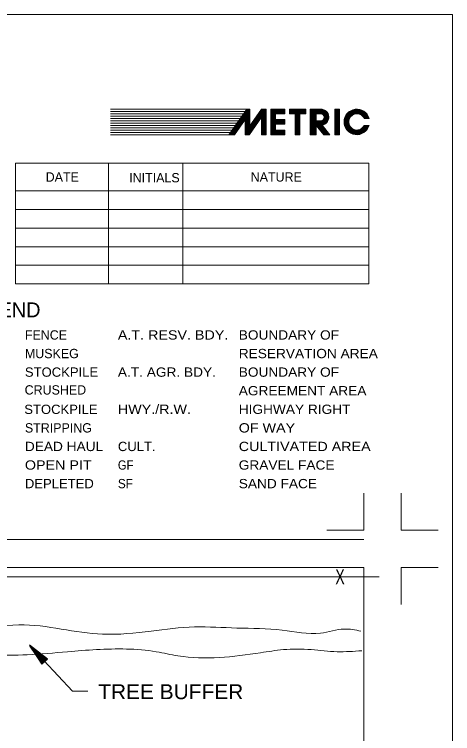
# Model space of a CAD drawing. Extents: x -496 to 480, y -450 to 700.
# Drawn here: x 214.3 to 450, y 312.9 to 700 of the extents above; entities that cross this region are included whole.
import ezdxf
from ezdxf.enums import TextEntityAlignment as Align

# ---------------------------------------------------------------- set-up
doc = ezdxf.new("R2010")
doc.units = 0
doc.header["$LTSCALE"] = 2
for name, color, linetype, lineweight in [('1', 7, 'Continuous', 13), ('3', 7, 'Continuous', 13), ('4', 7, 'Continuous', 25)]:
    doc.layers.add(name, color=color, linetype=linetype, lineweight=lineweight)

msp = doc.modelspace()

# ---------------------------------------------------------------- linework, layer by layer
at = {"layer": '1'}
for p, q in [((339.376, 648.989), (265.976, 648.989)), ((338.501, 647.739), (265.976, 647.739)), ((337.626, 646.489), (265.976, 646.489)), ((329.726, 635.239), (339.376, 648.989)), ((340.976, 640.064), (347.226, 648.989)), ((349.726, 648.989), (347.226, 648.989)), ((349.726, 635.239), (349.726, 648.989)), ((354.726, 646.489), (354.726, 643.364)), ((362.226, 648.989), (362.226, 646.489)), ((362.226, 646.489), (365.351, 646.489)), ((367.851, 646.489), (370.976, 646.489)), ((379.026, 648.989), (373.476, 648.989)), ((376.601, 646.489), (379.151, 646.489)), ((376.601, 642.739), (376.601, 646.489)), ((336.751, 645.239), (265.976, 645.239)), ((335.876, 643.989), (265.976, 643.989)), ((335.001, 642.739), (265.976, 642.739)), ((332.776, 635.239), (338.476, 643.364)), ((338.476, 635.239), (338.476, 643.389)), ((340.676, 635.264), (347.226, 644.614)), ((347.226, 635.239), (347.226, 644.614)), ((376.601, 642.739), (379.151, 642.739)), ((402.426, 643.989), (405.076, 643.989)), ((334.126, 641.489), (265.976, 641.489)), ((333.251, 640.239), (265.976, 640.239)), ((332.376, 638.989), (265.976, 638.989)), ((354.726, 640.864), (354.726, 637.739)), ((376.601, 640.239), (380.726, 635.239)), ((376.601, 635.239), (376.601, 640.239)), ((379.801, 640.289), (383.951, 635.239)), ((402.426, 640.239), (405.101, 640.239)), ((331.501, 637.739), (265.976, 637.739)), ((330.626, 636.489), (265.976, 636.489)), ((329.726, 635.239), (265.976, 635.239)), ((329.726, 635.239), (332.776, 635.239)), ((338.476, 635.239), (340.676, 635.239)), ((349.726, 635.239), (347.226, 635.239)), ((352.226, 635.239), (359.726, 635.239)), ((380.726, 635.239), (383.951, 635.239)), ((404.983, 619.973), (214.983, 619.973)), ((214.983, 619.973), (214.983, 554.973)), ((264.983, 619.973), (264.983, 554.973)), ((304.983, 619.973), (304.983, 554.973)), ((404.983, 554.973), (404.983, 619.973)), ((214.983, 604.973), (404.983, 604.973)), ((214.983, 594.973), (404.983, 594.973)), ((214.983, 584.973), (404.983, 584.973)), ((214.983, 574.973), (404.983, 574.973)), ((214.983, 564.973), (404.983, 564.973)), ((214.983, 554.973), (404.983, 554.973)), ((402.281, 422.339), (402.281, 442.339)), ((422.281, 422.339), (422.281, 442.339)), ((402.281, 422.339), (382.281, 422.339)), ((422.281, 422.339), (442.281, 422.339)), ((422.281, 402.339), (442.281, 402.339)), ((422.281, 402.339), (422.281, 382.339))]:
    msp.add_line(p, q, dxfattribs=at)
for points in [[(449.983, -450.027), (449.983, 399.973), (449.983, 699.973), (-450.017, 699.973), (-450.017, 49.973), (-450.017, -450.027)], [(329.901, 635.339), (339.401, 648.889), (340.901, 648.889), (340.901, 639.839), (347.251, 648.839), (349.626, 648.889), (349.676, 635.339), (347.351, 635.314), (347.301, 644.789), (340.576, 635.339), (338.576, 635.314), (338.576, 643.539), (332.701, 635.339), (330.076, 635.314), (339.501, 648.739), (340.801, 648.739), (340.776, 639.664), (347.276, 648.664), (349.526, 648.739), (349.651, 635.564), (347.501, 635.464), (347.426, 644.989), (340.526, 635.489), (338.726, 635.439), (338.676, 643.764), (332.651, 635.464), (330.301, 635.439), (339.576, 648.539), (340.651, 648.564), (340.651, 639.489), (347.351, 648.489), (349.301, 648.564), (349.476, 635.739), (347.726, 635.639), (347.626, 645.314), (340.451, 635.714), (338.926, 635.639), (338.876, 644.139), (332.501, 635.689), (330.701, 635.639)], [(330.701, 635.639), (339.651, 648.239), (340.326, 648.264), (340.476, 639.239), (347.526, 648.239), (349.126, 648.289), (349.226, 635.939), (348.001, 635.939), (347.851, 645.664), (340.326, 635.989), (339.151, 635.864), (339.126, 644.464), (332.401, 635.939), (331.076, 635.839), (339.651, 647.914), (340.151, 647.914), (340.251, 638.889), (347.601, 647.964), (348.926, 648.014), (349.026, 636.164), (348.251, 636.139), (348.051, 646.014), (340.226, 636.239), (339.351, 636.089), (339.326, 644.789), (332.226, 636.164), (331.476, 636.064), (339.701, 647.664), (339.926, 647.689), (340.126, 638.764), (347.751, 647.839), (348.701, 647.739), (348.826, 636.364), (348.476, 636.364), (348.176, 646.314), (340.126, 636.464), (339.551, 636.339), (339.426, 645.114), (332.201, 636.339), (331.851, 636.289)], [(331.851, 636.289), (339.701, 647.264), (339.926, 638.564), (347.826, 647.614), (348.451, 647.589), (348.701, 636.589), (348.251, 646.639), (340.126, 636.689), (339.726, 636.589), (339.576, 645.539), (332.301, 636.639), (339.526, 646.714), (339.576, 645.814), (335.101, 640.239), (339.401, 646.164), (339.401, 645.914), (338.176, 644.289)], [(340.976, 640.039), (340.976, 648.989), (339.376, 648.989)], [(339.901, 638.414), (339.926, 636.839), (348.276, 646.889), (348.326, 647.439), (347.951, 647.439), (340.126, 638.539), (340.151, 637.314), (348.176, 647.064), (348.051, 647.214), (340.326, 638.539), (340.401, 637.839), (347.851, 646.839), (340.501, 638.639), (340.526, 638.389), (344.426, 642.914)], [(352.226, 635.239), (352.226, 648.989), (359.726, 648.989)], [(352.376, 648.914), (359.651, 648.864), (359.676, 646.614), (354.626, 646.589), (354.626, 643.289), (359.651, 643.289), (359.651, 640.989), (354.651, 640.939), (354.626, 637.614), (359.676, 637.639), (359.651, 635.339), (352.351, 635.314), (352.376, 648.789), (359.551, 648.739), (359.551, 646.764), (354.501, 646.714), (354.501, 643.214), (359.551, 643.164), (359.551, 641.114), (354.551, 641.064), (354.526, 637.439), (359.551, 637.514), (359.501, 635.439), (352.501, 635.439), (352.576, 648.639), (359.401, 648.564), (359.426, 646.914), (354.376, 646.839), (354.351, 643.064), (359.426, 643.039), (359.376, 641.289), (354.401, 641.239), (354.376, 637.239), (359.401, 637.339), (359.376, 635.589), (352.701, 635.614), (352.726, 648.439), (359.226, 648.414), (359.251, 647.064), (354.251, 647.039)], [(354.251, 647.039), (354.176, 642.864), (359.251, 642.864), (359.176, 641.439), (354.251, 641.389), (354.201, 637.064), (359.201, 637.114), (359.176, 635.739), (352.926, 635.814), (352.976, 648.214), (359.026, 648.239), (359.076, 647.289), (354.076, 647.214), (354.001, 642.689), (359.051, 642.664), (359.026, 641.639), (354.076, 641.564), (354.026, 636.864), (359.051, 636.939), (359.026, 635.989), (353.126, 636.039), (353.226, 647.989), (358.801, 648.039), (358.826, 647.464), (353.926, 647.389), (353.851, 642.489), (358.876, 642.539), (358.801, 641.814), (353.951, 641.689), (353.851, 636.714), (358.901, 636.764), (358.901, 636.214), (353.351, 636.214), (353.476, 647.714), (358.601, 647.889), (358.626, 647.639), (353.776, 647.514), (353.751, 642.364), (358.626, 642.389), (358.601, 642.014)], [(358.601, 642.014), (353.826, 641.864), (353.726, 636.564), (358.701, 636.639), (358.701, 636.389), (353.551, 636.439), (353.626, 641.989), (358.376, 642.164), (358.326, 642.289), (353.576, 642.264), (353.676, 647.564)], [(359.726, 648.989), (359.726, 646.489), (354.726, 646.489)], [(370.976, 646.489), (370.976, 648.989), (362.226, 648.989)], [(362.351, 648.864), (370.851, 648.889), (370.851, 646.639), (367.701, 646.639), (367.751, 635.414), (365.451, 635.314), (365.451, 646.564), (362.351, 646.589), (362.351, 648.764), (370.801, 648.789), (370.726, 646.789), (367.601, 646.764), (367.676, 635.539), (365.576, 635.414), (365.626, 646.739), (362.476, 646.739), (362.476, 648.639), (370.626, 648.639), (370.576, 646.989), (367.426, 646.864), (367.526, 635.739), (365.751, 635.614), (365.776, 646.864), (362.701, 646.939), (362.726, 648.439), (370.451, 648.489), (370.376, 647.114), (367.276, 646.989), (367.376, 635.914), (365.901, 635.789), (365.951, 647.064), (362.901, 647.114), (362.901, 648.264), (370.201, 648.289), (370.201, 647.364), (367.076, 647.189), (367.226, 636.114), (366.126, 635.989), (366.101, 647.264), (363.101, 647.314)], [(363.101, 647.314), (363.151, 648.089), (369.976, 648.164), (369.926, 647.489), (366.876, 647.364), (367.026, 636.339), (366.351, 636.239), (366.276, 647.439), (363.326, 647.514), (363.401, 647.939), (369.751, 648.039), (369.701, 647.714), (366.726, 647.539), (366.851, 636.564), (366.476, 636.489), (366.426, 647.664), (363.701, 647.664), (363.751, 647.839), (369.451, 647.914), (369.426, 647.814), (366.601, 647.664), (366.626, 636.689)], [(367.851, 646.489), (367.851, 635.239), (365.351, 635.239), (365.351, 646.489)], [(373.476, 648.989), (373.476, 635.239), (376.601, 635.239)], [(373.601, 648.914), (378.976, 648.889), (380.101, 648.739), (381.101, 648.364), (381.826, 647.789), (382.451, 647.189), (382.901, 646.414), (383.301, 645.389), (383.301, 644.439), (383.126, 643.214), (382.651, 642.314), (381.926, 641.489), (381.051, 640.889), (380.401, 640.639), (379.651, 640.389), (380.026, 639.714), (380.576, 639.189), (383.701, 635.339), (380.801, 635.314), (376.501, 640.464), (376.526, 635.339), (373.551, 635.314), (373.551, 648.864), (379.026, 648.789), (380.076, 648.639), (380.926, 648.314), (382.276, 647.214), (383.151, 645.364), (383.026, 643.314), (382.601, 642.464), (381.901, 641.614), (381.051, 640.989), (379.576, 640.464), (383.501, 635.414), (380.951, 635.439), (376.351, 640.739), (376.401, 635.489), (373.701, 635.439), (373.701, 648.739), (379.151, 648.664), (380.076, 648.489), (380.851, 648.189), (382.126, 647.139), (383.026, 645.389), (382.951, 643.539), (382.501, 642.564), (381.901, 641.739), (381.051, 641.114), (379.401, 640.614), (383.201, 635.564), (381.001, 635.564), (376.226, 640.889), (376.276, 635.614), (373.826, 635.539), (373.826, 648.614), (379.126, 648.489), (380.676, 648.089), (382.026, 647.139), (382.876, 645.439), (382.801, 643.664), (382.401, 642.664), (381.801, 641.889), (380.951, 641.189), (379.226, 640.764), (382.901, 635.689), (381.101, 635.689), (376.051, 641.064), (376.126, 635.789), (373.976, 635.689), (373.976, 648.439), (379.101, 648.364), (380.551, 647.989), (381.851, 647.089), (382.776, 645.439), (382.701, 643.764), (382.326, 642.889), (381.726, 642.064), (380.901, 641.339), (379.026, 640.939), (382.601, 635.789), (381.126, 635.814), (375.876, 641.239), (375.976, 635.939), (374.126, 635.864), (374.126, 648.239), (379.026, 648.239), (380.251, 647.914), (381.676, 647.014), (382.576, 645.414), (382.601, 643.914), (382.276, 642.989), (381.651, 642.214), (380.826, 641.514), (378.851, 641.064), (382.351, 635.939), (381.176, 635.989), (375.776, 641.514), (375.826, 636.089), (374.251, 636.014), (374.276, 648.039), (378.976, 648.114)], [(378.976, 648.114), (379.026, 648.114), (380.201, 647.764), (381.526, 646.939), (382.401, 645.489), (382.401, 643.964), (382.076, 643.114), (380.826, 641.764), (378.601, 641.264), (382.001, 636.114), (381.351, 636.114), (375.676, 641.789), (375.676, 636.264), (374.376, 636.189), (374.451, 647.864), (378.926, 647.939), (380.176, 647.689), (381.351, 646.914), (382.151, 645.414), (382.201, 644.014), (381.901, 643.214), (380.726, 641.989), (378.401, 641.389), (381.676, 636.314), (381.501, 636.189), (375.526, 642.064), (375.476, 636.414), (374.551, 636.339), (374.651, 647.739), (379.976, 647.614), (381.151, 646.914), (382.001, 645.414), (382.051, 644.139), (381.726, 643.339), (380.651, 642.139), (378.226, 641.589), (381.401, 636.464), (375.401, 642.364), (375.376, 636.614), (374.676, 636.539), (374.901, 647.589), (379.826, 647.414), (380.851, 646.889), (381.801, 645.439), (381.901, 644.389), (381.576, 643.539), (380.576, 642.414), (378.051, 641.739), (380.676, 637.364), (375.376, 642.614), (375.226, 636.739), (374.851, 636.739), (375.076, 647.339), (379.601, 647.314), (380.676, 646.839), (381.626, 645.414), (381.726, 644.464), (381.376, 643.589), (380.501, 642.589), (377.826, 641.864), (380.026, 638.189), (375.251, 642.889), (375.076, 636.939), (374.926, 636.989), (375.226, 647.189), (379.526, 647.139), (380.551, 646.714), (381.401, 645.414), (381.551, 644.614), (380.376, 642.739), (377.726, 642.039), (379.276, 639.239), (375.351, 643.039), (375.426, 646.989), (379.476, 646.989), (380.526, 646.639), (381.251, 645.489), (381.326, 644.614), (380.276, 642.914), (377.551, 642.239), (378.601, 640.139), (375.576, 643.139), (375.676, 646.839), (379.451, 646.839), (380.476, 646.514), (381.101, 645.414), (381.051, 644.489), (380.876, 645.464), (380.501, 646.039), (380.151, 646.339), (379.476, 646.514), (378.751, 646.639), (377.601, 646.614), (376.476, 646.614), (376.501, 642.714), (378.626, 642.664), (377.376, 642.339), (378.126, 640.764), (375.726, 643.164), (375.876, 646.714), (379.451, 646.714)], [(376.026, 646.614), (375.901, 643.214), (377.551, 641.614), (377.251, 642.364), (377.776, 642.614), (376.826, 642.614), (377.201, 642.164)], [(376.151, 646.564), (376.051, 643.314), (376.376, 643.064), (376.351, 646.564), (376.251, 643.389)], [(379.451, 646.714), (379.401, 646.739), (380.451, 646.289)], [(386.776, 648.839), (388.951, 648.864), (389.001, 635.364), (386.701, 635.364), (386.676, 648.739), (388.851, 648.764), (388.876, 635.489), (386.826, 635.439), (386.801, 648.614), (388.776, 648.639), (388.776, 635.664), (386.976, 635.589), (386.926, 648.464), (388.626, 648.464), (388.601, 635.764), (387.126, 635.764), (387.101, 648.364), (388.501, 648.364), (388.451, 635.939), (387.301, 635.964), (387.301, 648.214), (388.401, 648.214), (388.301, 636.089), (387.426, 636.089), (387.476, 648.064), (388.251, 648.039), (388.151, 636.214), (387.576, 636.214), (387.676, 647.914), (388.126, 647.889), (388.001, 636.339), (387.776, 636.389), (387.826, 647.764), (387.976, 647.714), (387.901, 636.539)], [(404.901, 644.089), (404.451, 645.189), (403.851, 646.164), (403.151, 646.914), (402.301, 647.639), (401.151, 648.289), (400.126, 648.614), (398.801, 648.814), (397.351, 648.689), (395.876, 648.339), (394.601, 647.639), (393.601, 646.764), (392.776, 645.664), (392.176, 644.564), (391.801, 642.964), (391.801, 641.264), (392.176, 639.789), (392.726, 638.564), (393.351, 637.739), (394.101, 637.014), (394.976, 636.389), (395.901, 635.914), (397.126, 635.489), (398.726, 635.389), (400.151, 635.589), (401.301, 635.989), (402.326, 636.564), (403.326, 637.414), (404.001, 638.264), (404.426, 639.139), (404.801, 640.064), (402.526, 640.089), (401.776, 638.989), (400.776, 638.289), (399.801, 637.814), (398.476, 637.564), (397.026, 637.839), (396.126, 638.289), (395.276, 638.939), (394.551, 639.939), (394.076, 641.189), (394.051, 642.814), (394.276, 643.889), (394.901, 644.889), (395.601, 645.614), (396.476, 646.164), (397.376, 646.489), (398.426, 646.614), (399.526, 646.489), (400.426, 646.214), (401.176, 645.764), (401.801, 645.239), (402.301, 644.664), (402.576, 644.139), (404.726, 644.164), (404.251, 645.214), (403.651, 646.164), (402.276, 647.489), (401.126, 648.114), (399.351, 648.614), (397.876, 648.564), (396.551, 648.339), (395.226, 647.814), (394.351, 647.264), (393.451, 646.339), (392.676, 645.139), (392.176, 643.939), (391.976, 642.239), (392.076, 640.689), (392.576, 639.164), (393.476, 637.864), (394.526, 636.864), (395.701, 636.164), (397.201, 635.639), (398.626, 635.514), (400.251, 635.764), (401.276, 636.089), (402.301, 636.789), (403.176, 637.439), (403.726, 638.164), (404.376, 639.239), (404.551, 639.964), (402.626, 639.989), (402.076, 639.064), (400.751, 638.139), (399.826, 637.689), (398.526, 637.389), (396.976, 637.739), (395.601, 638.439), (394.651, 639.639), (394.076, 640.764), (393.876, 642.139), (394.151, 643.989), (394.726, 644.964), (395.826, 646.014), (397.051, 646.539), (398.351, 646.789), (399.826, 646.614), (401.026, 646.064), (401.701, 645.614), (402.226, 645.014)], [(402.226, 645.014), (402.301, 645.014), (402.676, 644.239), (404.476, 644.264), (404.026, 645.314), (402.876, 646.664), (401.901, 647.489), (400.851, 648.089), (399.251, 648.514), (396.976, 648.264), (395.201, 647.614), (394.051, 646.639), (393.151, 645.614), (392.526, 644.239), (392.176, 642.439), (392.326, 640.539), (392.676, 639.489), (392.951, 638.864), (393.701, 637.864), (394.851, 636.839), (397.101, 635.814), (398.651, 635.664), (401.026, 636.164), (403.076, 637.564), (403.901, 638.814), (404.326, 639.814), (403.476, 639.789), (402.726, 639.839), (402.201, 638.889), (400.776, 637.964), (399.526, 637.414), (398.251, 637.264), (396.651, 637.714), (395.476, 638.364), (394.451, 639.714), (393.901, 640.864), (393.701, 642.264), (393.976, 643.889), (394.651, 645.264), (395.701, 646.214), (397.376, 646.789), (398.851, 646.914), (400.251, 646.614), (401.626, 645.914), (402.426, 645.164), (402.801, 644.439), (404.226, 644.414), (403.426, 645.739), (402.676, 646.614), (401.826, 647.314), (400.851, 647.939), (399.276, 648.314), (397.051, 648.089), (395.226, 647.364), (393.976, 646.314), (393.201, 645.414), (392.651, 643.839), (392.426, 642.514), (392.451, 641.239), (392.651, 640.089), (393.101, 639.039), (393.651, 638.239), (394.376, 637.564), (395.226, 636.839), (396.351, 636.314), (397.451, 635.914), (398.701, 635.839), (400.826, 636.364), (402.976, 637.639), (403.801, 638.964), (404.026, 639.714), (402.851, 639.664), (402.326, 638.814), (401.226, 638.164), (399.651, 637.239), (398.226, 637.114), (397.101, 637.389), (395.976, 637.889), (394.801, 638.989), (394.101, 640.014), (393.601, 641.664), (393.676, 643.264), (394.101, 644.689), (395.376, 646.214), (396.876, 646.764), (398.751, 647.064), (400.326, 646.764), (401.751, 646.089), (402.651, 645.189), (402.951, 644.539), (403.876, 644.614), (403.051, 645.989), (402.201, 646.789), (400.851, 647.739), (399.376, 648.189), (397.151, 647.889), (395.451, 647.239), (394.076, 646.164), (393.251, 645.039), (392.701, 643.014), (392.651, 641.564)], [(392.651, 641.564), (392.676, 641.614), (392.951, 639.914), (393.451, 638.964), (394.051, 638.214), (394.926, 637.289), (395.951, 636.764), (396.601, 636.389), (397.801, 636.039), (398.776, 635.989), (400.726, 636.464), (402.951, 637.739), (403.651, 639.064), (403.726, 639.564), (403.026, 639.539), (402.576, 638.814), (399.876, 637.114), (398.026, 637.014), (396.051, 637.664), (394.476, 639.139), (393.526, 641.439), (393.651, 643.889), (394.476, 645.514), (395.726, 646.539), (397.351, 646.989), (398.701, 647.239), (400.476, 646.939), (401.751, 646.339), (402.526, 645.664), (402.851, 645.114), (403.076, 644.739), (403.551, 644.789), (402.926, 645.989), (401.801, 646.914), (400.676, 647.639), (399.376, 648.039), (397.176, 647.789), (395.676, 647.164), (394.226, 646.139), (393.501, 645.039), (392.901, 643.314), (392.826, 641.639), (393.126, 639.989), (393.851, 638.689), (394.951, 637.514), (396.001, 636.989), (396.726, 636.564), (398.626, 636.139), (400.701, 636.614), (402.776, 637.864), (403.476, 639.064), (403.601, 639.464), (403.251, 639.389), (402.751, 638.739), (400.001, 637.014), (398.001, 636.889), (395.901, 637.564), (394.326, 639.064), (393.376, 641.464), (393.576, 643.939), (394.301, 645.589), (395.526, 646.689), (398.576, 647.339), (400.751, 647.089), (401.751, 646.489), (402.601, 645.914), (403.076, 645.039), (403.326, 644.914), (402.851, 645.939), (400.926, 647.289), (399.526, 647.889), (397.401, 647.714), (395.626, 647.039), (394.251, 646.039), (393.576, 644.889), (393.026, 643.239), (392.951, 641.714), (393.276, 640.314), (393.801, 639.139), (394.376, 638.339), (395.076, 637.639), (396.901, 636.764), (398.651, 636.314), (400.576, 636.789), (402.601, 637.914), (403.351, 639.139), (402.501, 638.339), (401.601, 637.789), (400.101, 636.864), (398.051, 636.764), (395.801, 637.439), (394.176, 639.064), (393.226, 641.539), (393.501, 644.014), (394.126, 645.639), (395.451, 646.739), (397.026, 647.189), (398.576, 647.489), (399.776, 647.389), (400.526, 647.289), (399.551, 647.639)], [(399.551, 647.639), (398.601, 647.639), (397.451, 647.489), (395.901, 647.064)], [(354.726, 640.864), (359.726, 640.864), (359.726, 643.364), (354.726, 643.364)], [(402.751, 638.439), (402.076, 637.814), (400.676, 637.089), (399.226, 636.639), (398.501, 636.639), (396.951, 636.914), (395.751, 637.364), (394.201, 638.764), (393.101, 641.589), (393.401, 643.964), (393.901, 645.289)], [(354.726, 637.739), (359.726, 637.739), (359.726, 635.239)], [(402.281, -402.333), (402.281, 402.339), (-402.391, 402.339)]]:
    msp.add_lwpolyline(points, dxfattribs=at)
msp.add_lwpolyline([(386.601, 635.239), (386.601, 648.989), (389.101, 648.989), (389.101, 635.239)], close=True, dxfattribs=at)
for centre, radius, start, end in [((379.076, 644.614), 4.375, 279.51602, 90.65478), ((379.051, 644.614), 1.875, 272.29061, 86.94712), ((398.476, 642.114), 6.875, 15.80251, 344.19749), ((398.476, 642.114), 4.375, 25.39292, 334.60708)]:
    msp.add_arc(centre, radius, start, end, dxfattribs=at)
at = {"layer": '3'}
msp.add_line((402.281, 417.339), (-402.391, 417.339), dxfattribs=at)
msp.add_lwpolyline([(410.562, 397.339), (-397.391, 397.339), (-397.391, 23.005)], dxfattribs=at)
for points in [[(72.753, 368.814), (112.359, 370.322), (136.242, 369.767), (161.235, 367.548), (190.117, 368.102), (216.777, 371.431), (239.549, 369.212), (261.766, 366.438), (287.87, 368.102), (311.198, 370.322), (333.97, 369.767), (358.408, 368.657), (378.958, 366.993), (391.733, 369.212), (400.619, 368.102)], [(52.895, 357.406), (77.367, 357.007), (100.695, 355.343), (131.798, 355.343), (151.793, 359.226), (182.341, 357.007), (221.22, 355.343), (242.881, 357.007), (258.433, 358.117), (290.647, 357.007), (302.311, 354.788), (346.744, 356.452), (358.963, 358.117), (373.96, 358.117), (387.845, 357.007), (401.175, 357.562)]]:
    msp.add_spline(points, degree=3, dxfattribs=at)
at = {"layer": '4', "lineweight": 13}
msp.add_lwpolyline([(253.769, 335.739), (245.606, 335.739), (222.433, 360.463)], dxfattribs=at)
at = {"layer": '4'}
msp.add_lwpolyline([(222.433, 360.463), (229.18, 350.34), (232.099, 353.075)], close=True, dxfattribs=at)
msp.add_lwpolyline([(229.199, 350.492), (222.825, 360.044), (231.867, 353.082), (229.296, 350.643), (223.329, 359.506), (231.609, 353.107), (229.289, 350.871), (223.861, 358.939), (231.317, 353.099), (229.357, 351.113), (224.451, 358.279), (231.012, 353.14), (229.367, 351.421), (225.159, 357.489), (230.69, 353.105), (229.409, 351.755), (225.926, 356.64), (230.262, 353.088), (229.404, 352.106), (226.738, 355.679), (229.837, 353.162), (229.372, 352.52), (227.773, 354.605), (229.304, 353.196)], dxfattribs=at)

# ---------------------------------------------------------------- texts
at = {"layer": '1'}
for s, height, p in [('DATE', 5, (240.081, 609.973)), ('INITIALS', 5, (289.66, 609.584)), ('NATURE', 5, (355.16, 609.973)), ('LEGEND', 8, (206.378, 536.973))]:
    msp.add_text(s, height=height, dxfattribs=at).set_placement(p, align=Align.CENTER)
for s, p in [('FENCE', (219.983, 524.973)), ('MUSKEG', (219.983, 514.973)), ('CRUSHED', (219.856, 495.402)), ('STRIPPING', (219.983, 474.973))]:
    msp.add_text(s, height=5, dxfattribs=at).set_placement(p)
for s, width, p in [('A.T. RESV. BDY.', 1.15, (269.983, 524.973)), ('BOUNDARY OF', 1.1, (334.983, 524.973)), ('RESERVATION AREA', 1.1, (334.983, 514.973)), ('STOCKPILE', 1.05, (219.983, 504.973)), ('A.T. AGR. BDY.', 1.1, (269.983, 504.973)), ('BOUNDARY OF', 1.1, (334.983, 504.973)), ('AGREEMENT AREA', 1.1, (334.983, 494.973)), ('STOCKPILE', 1.05, (219.649, 484.941)), ('HWY./R.W.', 1.15, (269.983, 484.973)), ('HIGHWAY RIGHT', 1.1, (334.983, 484.973)), ('OF WAY', 1.15, (334.983, 474.973)), ('DEAD HAUL', 1.1, (219.983, 464.973)), ('CULT.', 1.05, (269.983, 464.973)), ('CULTIVATED AREA', 1.15, (334.983, 464.973)), ('OPEN PIT', 1.15, (219.983, 454.973)), ('GF', 0.9, (269.983, 454.973)), ('GRAVEL FACE', 1.1, (334.983, 454.973)), ('DEPLETED', 1.05, (219.983, 444.973)), ('SF', 0.95, (269.983, 444.973)), ('SAND FACE', 1.1, (334.983, 444.973))]:
    msp.add_text(s, height=5, dxfattribs=dict(at, width=width)).set_placement(p)
at = {"layer": '3', "width": 0.7}
msp.add_text('X', height=8, dxfattribs=at).set_placement((389.438, 393.307), align=Align.CENTER)
at = {"layer": '4', "width": 1.05}
msp.add_text('TREE BUFFER', height=8, dxfattribs=at).set_placement((298.423, 331.488), align=Align.CENTER)

doc.saveas('drawing.dxf')
